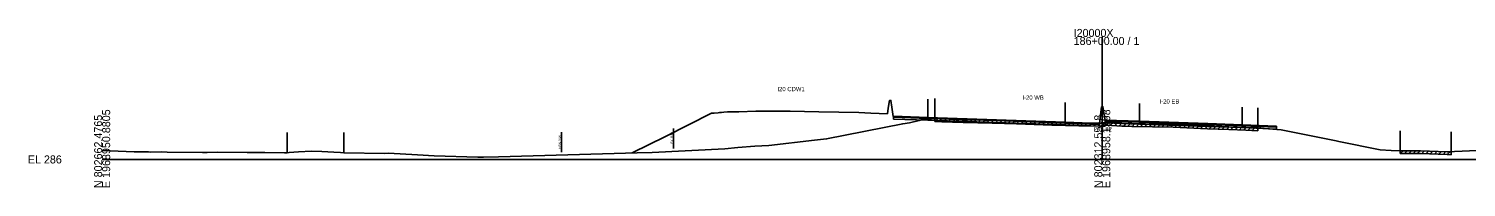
# Model space of a CAD drawing. Extents: x -4026 to 9638, y -10 to 19609.
# Drawn here: x 4974 to 5477, y 7490 to 7546 of the extents above; entities that cross this region are included whole.
import ezdxf

# ---------------------------------------------------------------- set-up
doc = ezdxf.new("R2010")
doc.units = 0
for name, color, linetype in [('Default', 7, 'Continuous'), ('RD_EX_Road', 7, 'Continuous'), ('RD_GPK_XS_Cell', 7, 'Continuous'), ('RD_PD_ALT1_TrvlWay', 7, 'Continuous'), ('RD_TX_Misc1', 7, 'Continuous'), ('RD_XS_Base', 7, 'Continuous'), ('RD_XS_ExGround', 7, 'Continuous'), ('RD_XS_ExPaveRet', 7, 'Continuous'), ('RD_XS_ExRW', 7, 'Continuous'), ('RD_XS_MedBWall', 7, 'Continuous'), ('RD_XS_NewRW', 7, 'Continuous'), ('RD_XS_Pave', 7, 'Continuous'), ('RD_XS_PaveOvlay', 7, 'Continuous'), ('RD_XS_TX_Elev_EX', 7, 'Continuous')]:
    doc.layers.add(name, color=color, linetype=linetype)

msp = doc.modelspace()

# ---------------------------------------------------------------- linework, layer by layer
at = {"layer": 'RD_EX_Road'}
for p, q in [((5291.44, 7521.26), (5291.44, 7514.26)), ((5404.39, 7518.04), (5404.39, 7511.04)), ((5064.76, 7509.35), (5064.76, 7502.35)), ((5084.53, 7509.36), (5084.53, 7502.36)), ((5454.26, 7510.02), (5454.26, 7503.02)), ((5472.14, 7509.65), (5472.14, 7502.65))]:
    msp.add_line(p, q, dxfattribs=at)
at = {"layer": 'RD_GPK_XS_Cell'}
for p, q in [((5350, 7500), (5350, 7542.77)), ((5000, 7500), (5350, 7500)), ((5350, 7500), (5700, 7500))]:
    msp.add_line(p, q, dxfattribs=at)
at = {"layer": 'RD_PD_ALT1_TrvlWay'}
for p, q in [((5289, 7521.06), (5289, 7514.06)), ((5337, 7519.87), (5337, 7512.87)), ((5363, 7519.49), (5363, 7512.49)), ((5399, 7518.23), (5399, 7511.23))]:
    msp.add_line(p, q, dxfattribs=at)
at = {"layer": 'RD_XS_Base'}
for points in [[(5277, 7514.76), (5277, 7514.09)], [(5289, 7514.35), (5277, 7514.76)], [(5277, 7514.09), (5289, 7513.68)], [(5337, 7512.72), (5313, 7513.54), (5289, 7514.35)], [(5289, 7514.35), (5289, 7513.68)], [(5289, 7514.35), (5289, 7514.35), (5289, 7513.68), (5289, 7513.68)], [(5289, 7513.68), (5313, 7512.87), (5337, 7512.05)], [(5337, 7512.05), (5337, 7512.72)], [(5349, 7512.25), (5337, 7512.72)], [(5337, 7512.05), (5349, 7511.58)], [(5349, 7511.58), (5349, 7512.25)], [(5351, 7512.74), (5351, 7513.41)], [(5351, 7513.41), (5363, 7512.99)], [(5363, 7512.32), (5351, 7512.74)], [(5363, 7512.32), (5363, 7512.99)], [(5363, 7512.99), (5387, 7512.18), (5399, 7511.77)], [(5399, 7511.1), (5387, 7511.51), (5363, 7512.32)], [(5399, 7511.77), (5399, 7511.77), (5399, 7511.1), (5399, 7511.1)], [(5399, 7511.1), (5399, 7511.77)], [(5399, 7511.77), (5411, 7511.29)], [(5411, 7510.62), (5399, 7511.1)], [(5411, 7511.29), (5411, 7510.62)]]:
    msp.add_lwpolyline(points, dxfattribs=at)
at = {"layer": 'RD_XS_ExGround'}
msp.add_lwpolyline([(5000, 7503.14), (5011.16, 7502.7), (5016.18, 7502.63), (5017, 7502.58), (5020.8, 7502.6), (5022.79, 7502.56), (5035.08, 7502.44), (5036.8, 7502.47), (5040.53, 7502.48), (5050.75, 7502.4), (5056.9, 7502.37), (5063.85, 7502.34), (5064.76, 7502.35), (5065.41, 7502.38), (5068.68, 7502.62), (5073.21, 7502.85), (5076.84, 7502.74), (5081.1, 7502.52), (5083.38, 7502.4), (5084.53, 7502.36), (5098.87, 7502.1), (5100.15, 7502.14), (5110.37, 7501.55), (5116.18, 7501.28), (5131.42, 7500.76), (5133.41, 7500.77), (5138.75, 7500.93), (5187.28, 7502.33), (5192.52, 7502.46), (5217.93, 7503.73), (5222.52, 7504.14), (5228.46, 7504.65), (5233.28, 7504.82), (5249.3, 7506.72), (5253.5, 7507.19), (5280.16, 7512.44), (5282.54, 7512.77), (5285.98, 7513.63), (5287.03, 7513.94), (5287.77, 7513.96), (5291.44, 7514.26), (5293.88, 7514.16), (5301.33, 7513.88), (5311.47, 7513.7), (5320.04, 7513.48), (5332.4, 7513.02), (5341.8, 7512.71), (5345.65, 7512.69), (5349.17, 7512.66), (5349.68, 7512.78), (5350, 7512.82), (5351.49, 7513.01), (5356.82, 7512.66), (5358.09, 7512.58), (5360.36, 7512.54), (5374.84, 7512.25), (5386.86, 7511.7), (5394.3, 7511.43), (5400.3, 7511.17), (5404.39, 7511.04), (5406.72, 7510.76), (5412.57, 7510.29), (5415.53, 7509.73), (5431.87, 7506.48), (5432.83, 7506.28), (5447.24, 7503.37), (5451.09, 7503.15), (5454.26, 7503.02), (5455.61, 7503.03), (5461.37, 7503.02), (5470.74, 7502.71), (5472.14, 7502.65), (5473.22, 7502.73), (5481.19, 7503.13)], dxfattribs=at)
at = {"layer": 'RD_XS_ExPaveRet'}
for p, q in [((5291.44, 7513.26), (5291.44, 7514.26)), ((5291.44, 7513.26), (5292.41, 7514.22)), ((5291.44, 7513.26), (5293.88, 7513.16)), ((5292.94, 7513.2), (5293.91, 7514.16)), ((5293.88, 7513.16), (5301.33, 7512.88)), ((5294.44, 7513.14), (5295.41, 7514.11)), ((5295.94, 7513.09), (5296.91, 7514.05)), ((5297.44, 7513.03), (5298.41, 7513.99)), ((5298.94, 7512.97), (5299.91, 7513.94)), ((5300.44, 7512.92), (5301.41, 7513.88)), ((5301.33, 7512.88), (5311.47, 7512.7)), ((5301.94, 7512.87), (5302.93, 7513.85)), ((5303.44, 7512.84), (5304.43, 7513.83)), ((5304.94, 7512.82), (5305.93, 7513.8)), ((5306.44, 7512.79), (5307.43, 7513.77)), ((5307.94, 7512.76), (5308.93, 7513.74)), ((5309.44, 7512.73), (5310.43, 7513.72)), ((5310.94, 7512.71), (5311.92, 7513.68)), ((5311.47, 7512.7), (5320.04, 7512.48)), ((5312.44, 7512.67), (5313.42, 7513.65)), ((5313.94, 7512.63), (5314.92, 7513.61)), ((5315.44, 7512.59), (5316.42, 7513.57)), ((5316.94, 7512.56), (5317.92, 7513.53)), ((5318.44, 7512.52), (5319.42, 7513.49)), ((5319.94, 7512.48), (5320.91, 7513.44)), ((5320.04, 7512.48), (5332.4, 7512.02)), ((5321.44, 7512.43), (5322.41, 7513.39)), ((5322.94, 7512.37), (5323.91, 7513.33)), ((5324.44, 7512.32), (5325.41, 7513.28)), ((5325.94, 7512.26), (5326.91, 7513.22)), ((5327.44, 7512.21), (5328.41, 7513.17)), ((5328.94, 7512.15), (5329.91, 7513.11)), ((5330.44, 7512.1), (5331.41, 7513.06)), ((5331.94, 7512.04), (5332.91, 7513.01)), ((5332.4, 7512.02), (5341.8, 7511.71)), ((5333.44, 7511.99), (5334.41, 7512.96)), ((5334.94, 7511.94), (5335.91, 7512.91)), ((5336.44, 7511.89), (5337.41, 7512.86)), ((5337.94, 7511.84), (5338.91, 7512.81)), ((5339.44, 7511.79), (5340.41, 7512.76)), ((5340.94, 7511.74), (5341.91, 7512.71)), ((5341.8, 7511.71), (5345.65, 7511.69)), ((5342.44, 7511.71), (5343.44, 7512.7)), ((5343.94, 7511.7), (5344.94, 7512.7)), ((5345.44, 7511.7), (5346.44, 7512.69)), ((5345.65, 7511.69), (5349.17, 7511.66)), ((5346.94, 7511.68), (5347.93, 7512.67)), ((5348.44, 7511.67), (5349.52, 7512.74)), ((5349.17, 7511.66), (5349.68, 7511.78)), ((5349.68, 7511.78), (5350, 7511.82)), ((5349.94, 7511.81), (5351.09, 7512.96)), ((5350, 7511.82), (5351.49, 7512.01)), ((5351.44, 7512), (5352.39, 7512.95)), ((5351.49, 7512.01), (5356.82, 7511.66)), ((5352.94, 7511.91), (5353.88, 7512.85)), ((5354.44, 7511.81), (5355.38, 7512.75)), ((5355.94, 7511.72), (5356.88, 7512.65)), ((5356.82, 7511.66), (5358.09, 7511.58)), ((5357.44, 7511.62), (5358.4, 7512.57)), ((5358.09, 7511.58), (5360.36, 7511.54)), ((5358.94, 7511.56), (5359.93, 7512.55)), ((5360.36, 7511.54), (5374.84, 7511.25)), ((5360.44, 7511.54), (5361.42, 7512.52)), ((5361.94, 7511.51), (5362.92, 7512.49)), ((5363.44, 7511.48), (5364.42, 7512.46)), ((5364.94, 7511.45), (5365.92, 7512.43)), ((5366.44, 7511.42), (5367.42, 7512.4)), ((5367.94, 7511.39), (5368.92, 7512.37)), ((5369.44, 7511.36), (5370.42, 7512.34)), ((5370.94, 7511.33), (5371.92, 7512.31)), ((5372.44, 7511.3), (5373.42, 7512.28)), ((5373.94, 7511.27), (5374.92, 7512.25)), ((5374.84, 7511.25), (5386.86, 7510.7)), ((5375.44, 7511.22), (5376.4, 7512.18)), ((5376.94, 7511.16), (5377.9, 7512.11)), ((5378.44, 7511.09), (5379.4, 7512.04)), ((5379.94, 7511.02), (5380.9, 7511.97)), ((5381.44, 7510.95), (5382.4, 7511.91)), ((5382.94, 7510.88), (5383.9, 7511.84)), ((5384.44, 7510.81), (5385.4, 7511.77)), ((5385.94, 7510.74), (5386.9, 7511.7)), ((5387.44, 7510.68), (5388.41, 7511.65)), ((5388.94, 7510.63), (5389.91, 7511.59)), ((5390.44, 7510.57), (5391.41, 7511.54)), ((5391.94, 7510.52), (5392.91, 7511.48)), ((5393.44, 7510.47), (5394.41, 7511.43)), ((5394.94, 7510.41), (5395.9, 7511.36)), ((5396.44, 7510.34), (5397.4, 7511.3)), ((5397.94, 7510.27), (5398.9, 7511.23)), ((5399.44, 7510.21), (5400.4, 7511.17)), ((5400.94, 7510.15), (5401.91, 7511.12)), ((5402.44, 7510.1), (5403.41, 7511.07)), ((5404.39, 7511.04), (5404.39, 7510.04)), ((5386.86, 7510.7), (5394.3, 7510.43)), ((5394.3, 7510.43), (5400.3, 7510.17)), ((5400.3, 7510.17), (5404.39, 7510.04)), ((5454.26, 7502.02), (5455.27, 7503.02)), ((5454.26, 7502.02), (5454.26, 7503.02)), ((5454.26, 7502.02), (5455.61, 7502.03)), ((5455.61, 7502.03), (5461.37, 7502.02)), ((5455.76, 7502.03), (5456.76, 7503.02)), ((5457.26, 7502.02), (5458.26, 7503.02)), ((5458.76, 7502.02), (5459.76, 7503.02)), ((5460.26, 7502.02), (5461.26, 7503.02)), ((5461.37, 7502.02), (5470.74, 7501.71)), ((5461.76, 7502), (5462.73, 7502.97)), ((5463.26, 7501.95), (5464.23, 7502.92)), ((5464.76, 7501.91), (5465.73, 7502.87)), ((5466.26, 7501.86), (5467.23, 7502.83)), ((5467.76, 7501.81), (5468.73, 7502.78)), ((5469.26, 7501.76), (5470.23, 7502.73)), ((5470.74, 7501.71), (5472.14, 7501.65)), ((5470.76, 7501.71), (5471.72, 7502.67)), ((5472.14, 7502.65), (5472.14, 7501.65))]:
    msp.add_line(p, q, dxfattribs=at)
at = {"layer": 'RD_XS_ExRW'}
msp.add_line((5200, 7503.83), (5200, 7510.83), dxfattribs=at)
at = {"layer": 'RD_XS_MedBWall'}
for points in [[(5349, 7512.58), (5349.75, 7518.41), (5350.25, 7518.41), (5351, 7513.74)], [(5349, 7511.58), (5349, 7512.58)], [(5351, 7511.58), (5349, 7511.58)], [(5351, 7513.74), (5351, 7511.58)]]:
    msp.add_lwpolyline(points, dxfattribs=at)
at = {"layer": 'RD_XS_NewRW'}
msp.add_line((5160.8, 7502.57), (5160.8, 7509.57), dxfattribs=at)
at = {"layer": 'RD_XS_Pave'}
for points in [[(5185.51, 7502.25), (5197.14, 7508.06), (5213.3, 7516.14), (5214.22, 7516.21), (5215.58, 7516.32), (5216.07, 7516.36), (5216.8, 7516.42), (5217.61, 7516.48), (5218.8, 7516.58), (5222.87, 7516.64), (5228.8, 7516.88), (5233.72, 7516.83), (5240.8, 7516.83), (5250.76, 7516.63), (5264.8, 7516.35), (5269, 7516.18), (5274.8, 7515.95), (5275.12, 7517.92), (5275.55, 7520.62), (5276.05, 7520.62), (5276.37, 7518.22), (5276.8, 7514.95)], [(5277, 7514.93), (5289, 7514.52)], [(5277, 7514.76), (5277, 7514.93)], [(5289, 7514.35), (5277, 7514.76)], [(5289, 7514.52), (5289, 7514.52), (5289, 7514.35), (5289, 7514.35)], [(5289, 7514.35), (5289, 7514.52)], [(5289, 7514.52), (5313, 7513.71), (5337, 7512.89)], [(5337, 7512.72), (5313, 7513.54), (5289, 7514.35)], [(5337, 7512.89), (5349, 7512.42)], [(5337, 7512.72), (5337, 7512.89)], [(5349, 7512.25), (5337, 7512.72)], [(5349, 7512.42), (5349, 7512.25)], [(5363, 7513.16), (5351, 7513.58)], [(5351, 7513.58), (5351, 7513.41)], [(5351, 7513.41), (5363, 7512.99)], [(5399, 7511.94), (5387, 7512.35), (5363, 7513.16)], [(5363, 7513.16), (5363, 7512.99)], [(5363, 7512.99), (5387, 7512.18), (5399, 7511.77)], [(5399, 7511.94), (5399, 7511.94), (5399, 7511.77), (5399, 7511.77)], [(5399, 7511.77), (5399, 7511.94)], [(5399, 7511.94), (5411, 7511.46)], [(5411, 7511.29), (5399, 7511.77)], [(5411, 7511.46), (5411, 7511.29)]]:
    msp.add_lwpolyline(points, dxfattribs=at)
at = {"layer": 'RD_XS_PaveOvlay'}
for points in [[(5277, 7515.1), (5289, 7514.69)], [(5277, 7514.93), (5277, 7515.1)], [(5289, 7514.52), (5277, 7514.93)], [(5289, 7514.69), (5313, 7513.87), (5337, 7513.06)], [(5289, 7514.52), (5289, 7514.69)], [(5289, 7514.69), (5289, 7514.69), (5289, 7514.52), (5289, 7514.52)], [(5337, 7512.89), (5313, 7513.71), (5289, 7514.52)], [(5337, 7513.06), (5337, 7512.89)], [(5337, 7513.06), (5349, 7512.58)], [(5349, 7512.42), (5337, 7512.89)], [(5349, 7512.58), (5349, 7512.42)], [(5363, 7513.33), (5351, 7513.74)], [(5351, 7513.74), (5351, 7513.58)], [(5351, 7513.58), (5363, 7513.16)], [(5399, 7512.1), (5387, 7512.51), (5363, 7513.33)], [(5363, 7513.33), (5363, 7513.16)], [(5363, 7513.16), (5387, 7512.35), (5399, 7511.94)], [(5399, 7511.94), (5399, 7512.1)], [(5399, 7512.1), (5411, 7511.62)], [(5399, 7512.1), (5399, 7512.1), (5399, 7511.94), (5399, 7511.94)], [(5411, 7511.46), (5399, 7511.94)], [(5411, 7511.62), (5411, 7511.46)]]:
    msp.add_lwpolyline(points, dxfattribs=at)

# ---------------------------------------------------------------- texts
at = {"layer": 'Default'}
msp.add_text('-', height=0.0001, dxfattribs=at).set_placement((5000, 7500))
at = {"layer": 'RD_GPK_XS_Cell'}
for s, p in [('186+00.00 / 1', (5340, 7539.97)), ('I20000X', (5340, 7542.77)), ('EL 286', (4974, 7498.6))]:
    msp.add_text(s, height=2.8, dxfattribs=at).set_placement(p)
for s, p in [('E 1968950.8805', (5002.8, 7490)), ('E 1968958.1398', (5352.8, 7490)), ('N 802662.4765', (5000, 7490)), ('N 802312.5518', (5350, 7490))]:
    msp.add_text(s, height=2.8, rotation=90, dxfattribs=at).set_placement(p)
at = {"layer": 'RD_TX_Misc1'}
for s, p in [('I20 CDW1', (5236.32, 7523.83)), ('I-20 WB', (5322.06, 7520.87)), ('I-20 EB', (5370.06, 7519.51))]:
    msp.add_text(s, height=1.5, dxfattribs=at).set_placement(p)
at = {"layer": 'RD_XS_ExRW'}
msp.add_text('EX. R/W ', height=0.75, rotation=90, dxfattribs=at).set_placement((5199.75, 7505.52))
at = {"layer": 'RD_XS_NewRW'}
msp.add_text('NEW R/W ', height=0.75, rotation=90, dxfattribs=at).set_placement((5160.55, 7503.71))
at = {"layer": 'RD_XS_TX_Elev_EX'}
msp.add_text('298.82', height=1.5, dxfattribs=at).set_placement((5347.05, 7509.82))

doc.saveas('drawing.dxf')
